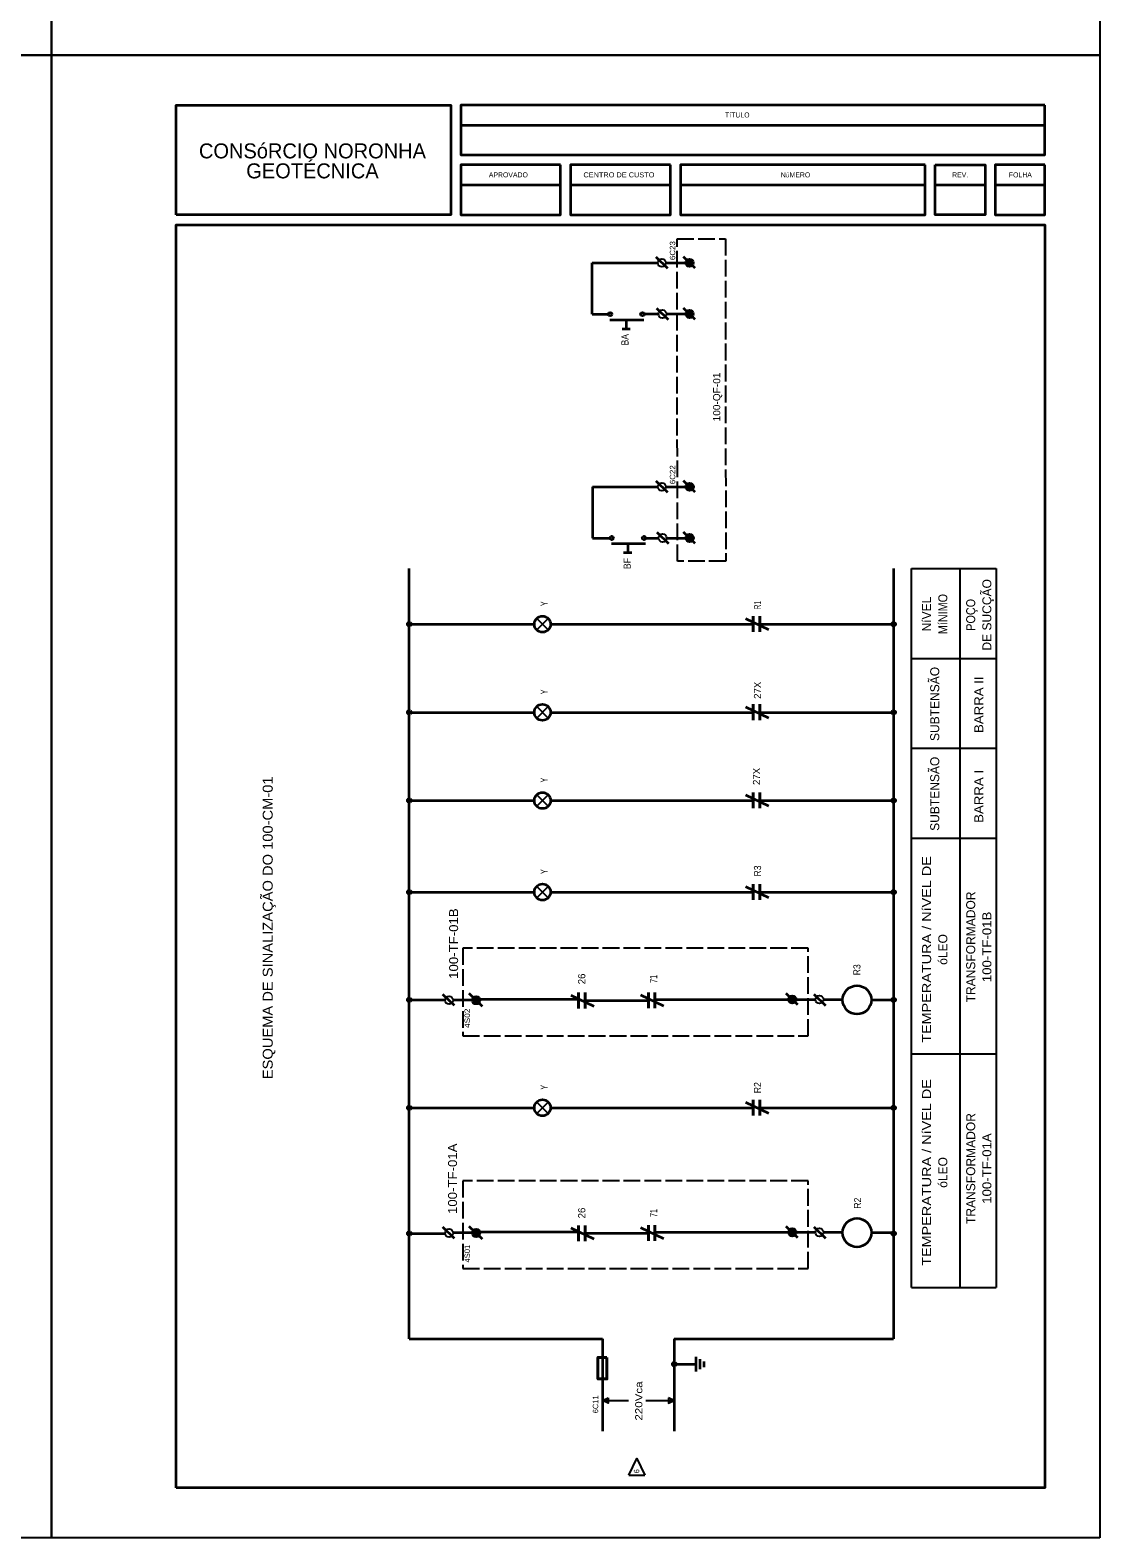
# Model space of a CAD drawing. Extents: x -4160 to -2690, y -474 to 714.
# Drawn here: x -2904 to -2689.8, y -473.5 to -171.5 of the extents above; entities that cross this region are included whole.
import ezdxf
from ezdxf.enums import TextEntityAlignment as Align

# ---------------------------------------------------------------- set-up
doc = ezdxf.new("R2010")
doc.units = 0
doc.header["$LTSCALE"] = 0.56
doc.linetypes.add('LONG_DASHED', pattern=[7.5, 6, -1.5])
for name, color, linetype, lineweight in [('1', 7, 'Continuous', 25), ('2', 7, 'Continuous', 25), ('5', 7, 'Continuous', 35)]:
    doc.layers.add(name, color=color, linetype=linetype, lineweight=lineweight)

msp = doc.modelspace()

# ---------------------------------------------------------------- hatches: boundary and pattern name
at = {"layer": '2'}
for points in [[(-2771.9467, -218.9377, 1), (-2771.9467, -217.3194, 1)], [(-2771.9467, -229.1839, 1), (-2771.9467, -227.5656, 1)], [(-2771.9268, -263.8107, 1), (-2771.9268, -262.1924, 1)], [(-2771.9268, -274.0569, 1), (-2771.9268, -272.4385, 1)], [(-2828.0779, -290.1356, 1), (-2828.0779, -290.8782, 1)], [(-2731.0635, -290.1356, 1), (-2731.0635, -290.8782, 1)], [(-2828.0779, -307.7978, 1), (-2828.0779, -308.5405, 1)], [(-2731.0635, -307.7978, 1), (-2731.0635, -308.5405, 1)], [(-2828.0779, -325.4601, 1), (-2828.0779, -326.2027, 1)], [(-2731.0635, -325.4601, 1), (-2731.0635, -326.2027, 1)], [(-2828.0779, -343.7978, 1), (-2828.0779, -344.5405, 1)], [(-2731.0635, -343.7978, 1), (-2731.0635, -344.5405, 1)], [(-2828.0779, -365.3978, 1), (-2828.0779, -366.1405, 1)], [(-2814.6853, -365.0326, 1), (-2814.6853, -366.651, 1)], [(-2751.3608, -366.5057, 1), (-2751.3608, -364.8873, 1)], [(-2731.0635, -365.3978, 1), (-2731.0635, -366.1405, 1)], [(-2828.0779, -386.9978, 1), (-2828.0779, -387.7405, 1)], [(-2731.0635, -386.9978, 1), (-2731.0635, -387.7405, 1)], [(-2828.0779, -412.1978, 1), (-2828.0779, -412.9405, 1)], [(-2814.6853, -411.6531, 1), (-2814.6853, -413.2715, 1)], [(-2751.3608, -413.1262, 1), (-2751.3608, -411.5078, 1)], [(-2731.0635, -412.1978, 1), (-2731.0635, -412.9405, 1)], [(-2774.9976, -438.3599, 1), (-2774.9976, -439.1026, 1)]]:
    msp.add_hatch(color=256, dxfattribs=at).paths.add_polyline_path(points)

# ---------------------------------------------------------------- linework, layer by layer
at = {"layer": '1'}
msp.add_line((-2784.0894, -460.96), (-2780.8925, -460.96), dxfattribs=at)
msp.add_lwpolyline([(-2784.0894, -460.96), (-2782.4909, -457.6135), (-2780.8925, -460.96)], dxfattribs=at)
at = {"layer": '2', "linetype": 'LONG_DASHED'}
for p, q in [((-2774.4328, -213.3114), (-2764.7599, -213.3114)), ((-2764.7599, -213.3114), (-2764.6948, -277.8913))]:
    msp.add_line(p, q, dxfattribs=at)
at = {"layer": '2', "lineweight": 35}
for p, q in [((-2776.3134, -219.2446), (-2778.6506, -216.9787)), ((-2773.2363, -216.8763), (-2770.8991, -219.1423)), ((-2791.4241, -218.1285), (-2778.179, -218.1285)), ((-2791.4241, -228.4064), (-2791.4241, -218.1285)), ((-2776.6964, -218.1285), (-2772.756, -218.1285)), ((-2791.4241, -228.4064), (-2788.224, -228.4064)), ((-2781.0199, -228.3748), (-2778.3062, -228.3748)), ((-2778.5822, -227.2174), (-2776.2451, -229.4834)), ((-2776.5612, -228.3748), (-2772.756, -228.3748)), ((-2773.2363, -227.1224), (-2770.8991, -229.3884)), ((-2787.8986, -229.5216), (-2781.0911, -229.5216)), ((-2785.4593, -231.3265), (-2783.833, -231.3265)), ((-2784.6461, -229.5216), (-2784.6461, -231.3265)), ((-2776.2935, -264.1177), (-2778.6307, -261.8517)), ((-2773.2164, -261.7493), (-2770.8793, -264.0152)), ((-2791.4043, -263.0015), (-2778.1591, -263.0015)), ((-2791.4043, -263.0015), (-2791.4043, -273.2794)), ((-2776.6765, -263.0015), (-2772.7361, -263.0015)), ((-2791.4043, -273.2794), (-2787.9099, -273.2794)), ((-2787.589, -274.3133), (-2780.7814, -274.3133)), ((-2784.3364, -274.3133), (-2784.3364, -276.118)), ((-2780.7058, -273.2478), (-2778.2943, -273.2478)), ((-2778.5233, -272.105), (-2776.1861, -274.371)), ((-2776.5414, -273.2478), (-2772.7361, -273.2478)), ((-2773.2164, -271.9954), (-2770.8793, -274.2614)), ((-2785.1495, -276.118), (-2783.5232, -276.118)), ((-2828.0779, -433.6311), (-2828.0779, -279.3691)), ((-2731.0636, -279.3691), (-2731.0636, -433.6311)), ((-2756.0716, -291.6469), (-2760.6785, -289.439)), ((-2828.0779, -290.5069), (-2803.0321, -290.5069)), ((-2799.7777, -290.5069), (-2759.1715, -290.5069)), ((-2757.864, -290.5069), (-2731.0636, -290.5069)), ((-2756.0716, -309.3093), (-2760.6785, -307.1014)), ((-2828.0779, -308.1691), (-2803.0321, -308.1691)), ((-2799.7777, -308.1691), (-2759.1715, -308.1691)), ((-2757.864, -308.1691), (-2731.0636, -308.1691)), ((-2828.0779, -325.8315), (-2803.0321, -325.8315)), ((-2799.7777, -325.8315), (-2759.1715, -325.8315)), ((-2756.0716, -326.9715), (-2760.6785, -324.7636)), ((-2757.864, -325.8315), (-2731.0636, -325.8315)), ((-2828.0779, -344.1691), (-2803.0321, -344.1691)), ((-2799.7777, -344.1691), (-2759.1715, -344.1691)), ((-2756.0716, -345.3093), (-2760.6785, -343.1014)), ((-2757.864, -344.1691), (-2731.0636, -344.1691)), ((-2821.3986, -364.5873), (-2819.0614, -366.8532)), ((-2813.3957, -367.0941), (-2816.0566, -364.5143)), ((-2791.0791, -367.0677), (-2795.686, -364.8598)), ((-2777.0761, -367.0043), (-2781.683, -364.7964)), ((-2752.6504, -364.4442), (-2750.3132, -366.7102)), ((-2744.6475, -366.9511), (-2746.9847, -364.6852)), ((-2828.0779, -365.7691), (-2820.9182, -365.7691)), ((-2819.3029, -365.7691), (-2815.4306, -365.7691)), ((-2794.179, -365.6988), (-2813.8761, -365.6988)), ((-2792.8715, -365.8572), (-2780.176, -365.8572)), ((-2778.8685, -365.6988), (-2752.1701, -365.6988)), ((-2750.5516, -365.6965), (-2746.7463, -365.6965)), ((-2745.1279, -365.6988), (-2741.2792, -365.6988)), ((-2735.523, -365.7691), (-2731.0636, -365.7691)), ((-2756.0716, -388.5093), (-2760.6785, -386.3014)), ((-2828.0779, -387.3691), (-2803.0321, -387.3691)), ((-2799.7777, -387.3691), (-2759.1715, -387.3691)), ((-2757.864, -387.3691), (-2731.0636, -387.3691)), ((-2828.0779, -412.5691), (-2820.9182, -412.5691)), ((-2821.3986, -411.2077), (-2819.0614, -413.4737)), ((-2819.3029, -412.3897), (-2815.4306, -412.3897)), ((-2813.3957, -413.7147), (-2816.0566, -411.1348)), ((-2794.179, -412.3193), (-2813.8761, -412.3193)), ((-2791.0791, -413.6881), (-2795.686, -411.4802)), ((-2792.8715, -412.4777), (-2780.176, -412.4777)), ((-2777.0761, -413.6247), (-2781.683, -411.4169)), ((-2778.8685, -412.3193), (-2752.1701, -412.3193)), ((-2752.6504, -411.0647), (-2750.3132, -413.3307)), ((-2750.5516, -412.317), (-2746.7463, -412.317)), ((-2744.6475, -413.5716), (-2746.9847, -411.3056)), ((-2745.1279, -412.3193), (-2741.2792, -412.3193)), ((-2735.523, -412.3897), (-2731.0636, -412.3897)), ((-2828.0779, -433.6311), (-2789.3976, -433.6311)), ((-2789.3976, -433.6311), (-2789.3976, -452.1605)), ((-2774.9976, -433.6311), (-2731.0636, -433.6311)), ((-2774.9976, -433.6311), (-2774.9976, -452.1605)), ((-2770.6435, -440.215), (-2770.6435, -437.2474)), ((-2769.8506, -439.7614), (-2769.8506, -437.7551)), ((-2774.9976, -438.7312), (-2770.6435, -438.7312)), ((-2769.0159, -439.3017), (-2769.0159, -438.2148))]:
    msp.add_line(p, q, dxfattribs=at)
at = {"layer": '2'}
for p, q in [((-2727.4636, -423.3691), (-2727.4636, -279.3691)), ((-2727.4636, -279.3691), (-2710.5254, -279.3691)), ((-2717.7254, -423.3691), (-2717.7254, -279.3691)), ((-2710.5254, -279.3691), (-2710.5254, -423.3691)), ((-2802.5556, -289.3562), (-2800.2543, -291.6575)), ((-2802.5556, -291.6575), (-2800.2544, -289.3562)), ((-2727.4636, -297.3691), (-2710.5254, -297.3691)), ((-2802.5556, -307.0185), (-2800.2543, -309.3197)), ((-2802.5556, -309.3197), (-2800.2544, -307.0186)), ((-2727.4636, -315.3691), (-2710.5254, -315.3691)), ((-2802.5556, -324.6807), (-2800.2543, -326.982)), ((-2802.5556, -326.982), (-2800.2544, -324.6808)), ((-2727.4636, -333.3691), (-2710.5254, -333.3691)), ((-2802.5556, -343.0185), (-2800.2543, -345.3197)), ((-2802.5556, -345.3197), (-2800.2544, -343.0186)), ((-2727.4636, -376.5691), (-2710.5254, -376.5691)), ((-2802.5556, -386.2185), (-2800.2543, -388.5197)), ((-2802.5556, -388.5197), (-2800.2544, -386.2186)), ((-2727.4636, -423.3691), (-2710.5254, -423.3691)), ((-2789.3976, -446.0302), (-2784.1619, -446.0302)), ((-2780.7292, -446.0302), (-2774.9976, -446.0302))]:
    msp.add_line(p, q, dxfattribs=at)
at = {"layer": '2', "lineweight": 40}
for p, q in [((-2759.1715, -292.0426), (-2759.1715, -288.8939)), ((-2757.864, -292.0426), (-2757.864, -288.8939)), ((-2759.1715, -309.7049), (-2759.1715, -306.5562)), ((-2757.864, -309.7049), (-2757.864, -306.5562)), ((-2759.1715, -327.3671), (-2759.1715, -324.2184)), ((-2757.864, -327.3671), (-2757.864, -324.2184)), ((-2759.1715, -345.7049), (-2759.1715, -342.5562)), ((-2757.864, -345.7049), (-2757.864, -342.5562)), ((-2794.179, -367.4633), (-2794.179, -364.3146)), ((-2792.8715, -367.4633), (-2792.8715, -364.3146)), ((-2780.176, -367.3999), (-2780.176, -364.2512)), ((-2778.8685, -367.3999), (-2778.8685, -364.2512)), ((-2759.1715, -388.9049), (-2759.1715, -385.7562)), ((-2757.864, -388.9049), (-2757.864, -385.7562)), ((-2794.179, -414.0837), (-2794.179, -410.9351)), ((-2792.8715, -414.0837), (-2792.8715, -410.9351)), ((-2780.176, -414.0204), (-2780.176, -410.8717)), ((-2778.8685, -414.0204), (-2778.8685, -410.8717))]:
    msp.add_line(p, q, dxfattribs=at)
at = {"layer": '2', "linetype": 'LONG_DASHED'}
msp.add_lwpolyline([(-2764.6948, -277.8913), (-2774.3677, -277.8913), (-2774.4328, -213.3114)], dxfattribs=at)
for points in [[(-2817.3571, -372.9691), (-2748.2052, -372.9691), (-2748.2052, -355.3956), (-2817.3571, -355.3956)], [(-2817.3571, -419.5897), (-2748.2052, -419.5897), (-2748.2052, -402.0161), (-2817.3571, -402.0161)]]:
    msp.add_lwpolyline(points, close=True, dxfattribs=at)
at = {"layer": '2', "lineweight": 40}
msp.add_lwpolyline([(-2788.4906, -437.3668), (-2788.4906, -441.6694), (-2790.3045, -441.6694), (-2790.3045, -437.3668)], close=True, dxfattribs=at)
at = {"layer": '2'}
for points in [[(-2788.2521, -445.4861), (-2788.2521, -446.5745), (-2789.3976, -446.0302)], [(-2776.1431, -445.4861), (-2776.1431, -446.5745), (-2774.9976, -446.0302)]]:
    msp.add_lwpolyline(points, close=True, dxfattribs=at)
for centre in [(-2777.5056, -218.1286), (-2771.9467, -218.1286), (-2777.3705, -228.3724), (-2771.9467, -228.3747), (-2777.4857, -263.0015), (-2771.9268, -263.0015), (-2777.3506, -273.2454), (-2771.9268, -273.2477), (-2820.109, -365.8395), (-2814.6853, -365.8418), (-2751.3608, -365.6965), (-2745.9371, -365.6988), (-2820.109, -412.46), (-2814.6853, -412.4623), (-2751.3608, -412.317), (-2745.9371, -412.3193)]:
    msp.add_circle(centre, 0.8092, dxfattribs=at)
at = {"layer": '2', "lineweight": 35}
for centre, radius in [((-2787.8614, -228.4124), 0.36), ((-2781.3815, -228.4124), 0.36), ((-2787.5517, -273.252), 0.36), ((-2781.0717, -273.252), 0.36), ((-2801.4049, -290.5069), 1.6272), ((-2828.0779, -290.5069), 0.3713), ((-2731.0635, -290.5069), 0.3713), ((-2828.0779, -308.1692), 0.3713), ((-2801.4049, -308.1692), 1.6272), ((-2731.0635, -308.1692), 0.3713), ((-2828.0779, -325.8314), 0.3713), ((-2801.4049, -325.8314), 1.6272), ((-2731.0635, -325.8314), 0.3713), ((-2828.0779, -344.1692), 0.3713), ((-2801.4049, -344.1692), 1.6272), ((-2731.0635, -344.1692), 0.3713), ((-2828.0779, -365.7692), 0.3713), ((-2738.4015, -365.7692), 2.8785), ((-2731.0635, -365.7692), 0.3713), ((-2801.4049, -387.3692), 1.6272), ((-2828.0779, -387.3692), 0.3713), ((-2731.0635, -387.3692), 0.3713), ((-2738.4015, -412.3897), 2.8785), ((-2828.0779, -412.5692), 0.3713), ((-2731.0635, -412.5692), 0.3713), ((-2774.9976, -438.7312), 0.3713)]:
    msp.add_circle(centre, radius, dxfattribs=at)
at = {"layer": '5'}
for p, q in [((-2817.7642, -190.52), (-2700.7642, -190.52)), ((-2817.7642, -202.52), (-2797.7642, -202.52)), ((-2795.7642, -202.52), (-2775.7642, -202.52)), ((-2773.7642, -202.52), (-2724.7642, -202.52)), ((-2722.7642, -202.52), (-2712.7642, -202.52)), ((-2710.7642, -202.52), (-2700.7642, -202.52))]:
    msp.add_line(p, q, dxfattribs=at)
at = {"layer": '5', "lineweight": 25}
for points in [[(-2899.7642, -176.52), (-3109.7642, -176.52), (-3109.7642, 120.48), (-2899.7642, 120.48)], [(-2689.7642, -176.52), (-2899.7642, -176.52), (-2899.7642, 120.48), (-2689.7642, 120.48)], [(-2899.7642, -473.52), (-3109.7642, -473.52), (-3109.7642, -176.52), (-2899.7642, -176.52)], [(-2689.7642, -473.52), (-2899.7642, -473.52), (-2899.7642, -176.52), (-2689.7642, -176.52)]]:
    msp.add_lwpolyline(points, close=True, dxfattribs=at)
at = {"layer": '5'}
for points in [[(-2874.7642, -208.52), (-2874.7642, -186.52), (-2819.7642, -186.52), (-2819.7642, -208.52)], [(-2700.7642, -186.52), (-2817.7642, -186.52), (-2817.7642, -196.52), (-2700.7642, -196.52)], [(-2797.7642, -198.52), (-2817.7642, -198.52), (-2817.7642, -208.52), (-2797.7642, -208.52)], [(-2775.7642, -198.52), (-2795.7642, -198.52), (-2795.7642, -208.52), (-2775.7642, -208.52)], [(-2724.7642, -198.52), (-2773.7642, -198.52), (-2773.7642, -208.52), (-2724.7642, -208.52)], [(-2722.7642, -198.52), (-2712.7642, -198.52), (-2712.7642, -208.52), (-2722.7642, -208.52)], [(-2700.7642, -198.52), (-2710.7642, -198.52), (-2710.7642, -208.52), (-2700.7642, -208.52)], [(-2874.7642, -463.52), (-2874.7642, -210.52), (-2700.7642, -210.52), (-2700.7642, -463.52)]]:
    msp.add_lwpolyline(points, close=True, dxfattribs=at)

# ---------------------------------------------------------------- texts
at = {"layer": '2'}
for s, height, width, p in [('6C23', 1.08, 1.1, (-2774.8156, -215.6764)), ('BA', 1.44, 0.9, (-2784.16, -233.527)), ('100-QF-01', 1.44, 1.05, (-2765.7977, -244.9995)), ('6C22', 1.08, 1.1, (-2774.8156, -260.5704)), ('BF', 1.44, 0.9, (-2783.7247, -278.3666)), ('Y', 1.44, 0.7, (-2800.3412, -286.4101)), ('R1', 1.44, 0.55, (-2757.6119, -286.6906)), ('MíNIMO', 1.8, 0.9, (-2720.3175, -288.4812)), ('POÇO', 1.8, 0.9, (-2714.7341, -288.6348)), ('BARRA II', 1.8, 1.1, (-2713.1141, -306.6347)), ('Y', 1.44, 0.7, (-2800.3412, -304.0723)), ('BARRA I', 1.8, 1.1, (-2713.1141, -325.0015)), ('ESQUEMA DE SINALIZAÇÃO DO 100-CM-01', 2, 1.1, (-2855.4337, -351.3313)), ('Y', 1.44, 0.7, (-2800.3412, -321.7346)), ('TEMPERATURA / NíVEL DE', 1.8, 1.2, (-2723.5575, -355.6627)), ('Y', 1.44, 0.7, (-2800.3412, -340.0723)), ('R3', 1.44, 0.9, (-2757.6119, -339.948)), ('100-TF-01B', 1.8, 1.1, (-2818.3008, -354.4948)), ('100-TF-01B', 1.8, 1.1, (-2711.4941, -355.1543)), ('R3', 1.44, 0.9, (-2737.7101, -359.7339)), ('71', 1.44, 0.6, (-2778.4256, -361.567)), ('4S02', 1.08, 1.15, (-2815.9399, -369.4438)), ('Y', 1.44, 0.7, (-2800.3412, -383.2723)), ('R2', 1.44, 0.9, (-2757.6119, -383.3495)), ('TEMPERATURA / NíVEL DE', 1.8, 1.2, (-2723.5575, -400.329)), ('100-TF-01A', 1.8, 1.1, (-2711.4941, -399.5457)), ('100-TF-01A', 1.8, 1.1, (-2818.5195, -401.5933)), ('R2', 1.44, 0.9, (-2737.5816, -406.4826)), ('71', 1.44, 0.6, (-2778.4256, -408.4558)), ('4S01', 1.08, 1.05, (-2815.9399, -416.5938)), ('220Vca', 1.44, 1.2, (-2781.3948, -446.1093)), ('6', 1.08, 0.85, (-2782.023, -460.1683))]:
    msp.add_text(s, height=height, rotation=90, dxfattribs=dict(at, width=width)).set_placement(p, align=Align.CENTER)
for s, height, p in [('DE SUCÇÃO', 1.8, (-2711.4941, -288.6347)), ('NíVEL', 1.8, (-2723.5575, -288.4812)), ('SUBTENSÃO', 1.8, (-2721.9375, -306.4812)), ('27X', 1.44, (-2757.6119, -303.748)), ('27X', 1.44, (-2757.8136, -321.007)), ('SUBTENSÃO', 1.8, (-2721.9375, -324.4812)), ('TRANSFORMADOR', 1.8, (-2714.7341, -355.1543)), ('óLEO', 1.8, (-2720.3175, -355.6628)), ('26', 1.44, (-2792.8256, -361.5668)), ('TRANSFORMADOR', 1.8, (-2714.7341, -399.5458)), ('óLEO', 1.8, (-2720.3175, -400.329)), ('26', 1.44, (-2792.8256, -408.4554)), ('6C11', 1.08, (-2790.2435, -446.7823))]:
    msp.add_text(s, height=height, rotation=90, dxfattribs=at).set_placement(p, align=Align.CENTER)
at = {"layer": '5'}
for s, height, p in [('TíTULO', 1, (-2762.3847, -189.009)), ('CONSóRCIO NORONHA', 3, (-2847.4749, -197.2039)), ('GEOTÉCNICA', 3, (-2847.475, -201.2039)), ('APROVADO', 1, (-2808.2387, -201.0027)), ('REV.', 1, (-2717.7443, -201.0077)), ('FOLHA', 1, (-2705.6809, -201.0077))]:
    msp.add_text(s, height=height, dxfattribs=at).set_placement(p, align=Align.CENTER)
for s, width, p in [('CENTRO DE CUSTO', 1.1, (-2786.0934, -201.0027)), ('NúMERO', 0.95, (-2750.7227, -201.0077))]:
    msp.add_text(s, height=1, dxfattribs=dict(at, width=width)).set_placement(p, align=Align.CENTER)

doc.saveas('drawing.dxf')
